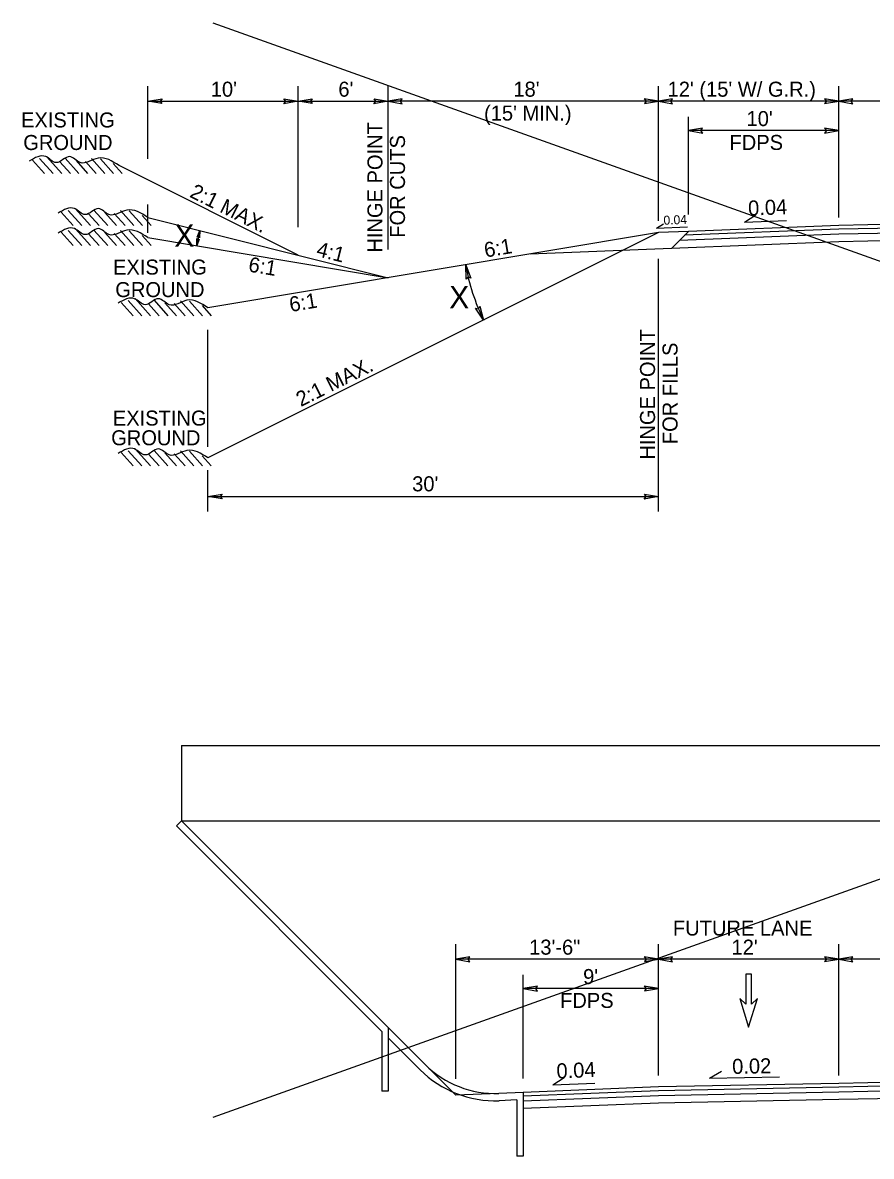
# Model space of a CAD drawing. Extents: x 1553195 to 1553792, y 810516 to 810787.
# Drawn here: x 1553435.9 to 1553492.4, y 810531.1 to 810606.6 of the extents above; entities that cross this region are included whole.
import ezdxf

# ---------------------------------------------------------------- set-up
doc = ezdxf.new("R2010")
doc.units = 0
for name, color, linetype in [('Prop Dimension', 7, 'Continuous'), ('Prop DSN Text', 7, 'Continuous'), ('Prop Pavement Schedule Description CELL', 7, 'Continuous'), ('Prop Typical Section', 7, 'Continuous'), ('Sheet Sticker Incomplete CELL', 7, 'Continuous'), ('Typical Arrow Superelevation CELL', 7, 'Continuous'), ('Typical Pavement Slope CELL', 7, 'Continuous'), ('Typical Text General CELL', 7, 'Continuous'), ('z - Construction', 7, 'Continuous')]:
    doc.layers.add(name, color=color, linetype=linetype)

msp = doc.modelspace()

# ---------------------------------------------------------------- linework, layer by layer
at = {"layer": 'Prop Dimension'}
for p, q in [((1553483.925, 810593.325), (1553484.698, 810593.813)), ((1553483.925, 810593.325), (1553486.72, 810593.436)), ((1553478.066, 810592.922), (1553478.53, 810593.215)), ((1553478.066, 810592.922), (1553480.136, 810593.004)), ((1553481.608, 810536.34), (1553482.391, 810536.814)), ((1553471.163, 810535.891), (1553471.936, 810536.38)), ((1553471.163, 810535.891), (1553473.958, 810536.003)), ((1553481.608, 810536.34), (1553486.268, 810536.434))]:
    msp.add_line(p, q, dxfattribs=at)
at = {"layer": 'Prop DSN Text'}
for points in [[(1553445.143, 810601.212), (1553444.206, 810601.374), (1553445.148, 810601.54), (1553445.028, 810601.374)], [(1553453.268, 810601.535), (1553454.206, 810601.374), (1553453.263, 810601.207), (1553453.383, 810601.374)], [(1553455.143, 810601.212), (1553454.206, 810601.374), (1553455.148, 810601.54), (1553455.028, 810601.374)], [(1553459.268, 810601.535), (1553460.206, 810601.374), (1553459.263, 810601.207), (1553459.383, 810601.374)], [(1553461.143, 810601.535), (1553460.206, 810601.374), (1553461.148, 810601.207), (1553461.028, 810601.374)], [(1553477.268, 810601.212), (1553478.206, 810601.374), (1553477.263, 810601.54), (1553477.383, 810601.374)], [(1553479.143, 810601.535), (1553478.206, 810601.374), (1553479.148, 810601.207), (1553479.028, 810601.374)], [(1553489.268, 810601.212), (1553490.206, 810601.374), (1553489.263, 810601.54), (1553489.383, 810601.374)], [(1553491.143, 810601.535), (1553490.206, 810601.374), (1553491.148, 810601.207), (1553491.028, 810601.374)], [(1553481.143, 810599.579), (1553480.206, 810599.418), (1553481.148, 810599.251), (1553481.028, 810599.418)], [(1553489.268, 810599.257), (1553490.206, 810599.418), (1553489.263, 810599.585), (1553489.383, 810599.418)], [(1553447.488, 810592.322), (1553447.675, 810592.76), (1553447.647, 810592.282), (1553447.58, 810592.36)], [(1553447.63, 810592.197), (1553447.465, 810591.751), (1553447.469, 810592.229), (1553447.54, 810592.155)], [(1553465.394, 810589.537), (1553465.368, 810590.488), (1553465.717, 810589.596), (1553465.53, 810589.681)], [(1553466.319, 810587.726), (1553466.565, 810586.807), (1553466.019, 810587.593), (1553466.221, 810587.554)], [(1553449.143, 810574.9), (1553448.206, 810575.062), (1553449.148, 810575.228), (1553449.028, 810575.062)], [(1553477.268, 810575.223), (1553478.206, 810575.062), (1553477.263, 810574.895), (1553477.383, 810575.062)], [(1553465.643, 810544.426), (1553464.706, 810544.264), (1553465.648, 810544.098), (1553465.528, 810544.264)], [(1553477.268, 810544.103), (1553478.206, 810544.264), (1553477.263, 810544.431), (1553477.383, 810544.264)], [(1553479.143, 810544.426), (1553478.206, 810544.264), (1553479.148, 810544.098), (1553479.028, 810544.264)], [(1553489.268, 810544.103), (1553490.206, 810544.264), (1553489.263, 810544.431), (1553489.383, 810544.264)], [(1553491.143, 810544.426), (1553490.206, 810544.264), (1553491.148, 810544.098), (1553491.028, 810544.264)], [(1553470.143, 810542.47), (1553469.206, 810542.309), (1553470.148, 810542.142), (1553470.028, 810542.309)], [(1553477.268, 810542.147), (1553478.206, 810542.309), (1553477.263, 810542.476), (1553477.383, 810542.309)]]:
    msp.add_lwpolyline(points, close=True, dxfattribs=at)
at = {"layer": 'Prop Pavement Schedule Description CELL'}
for p, q in [((1553460.206, 810591.507), (1553460.206, 810602.374)), ((1553478.206, 810593.404), (1553478.206, 810602.374)), ((1553480.206, 810593.822), (1553480.206, 810600.332)), ((1553478.206, 810574.062), (1553478.206, 810590.871)), ((1553448.206, 810578.372), (1553448.206, 810586.148)), ((1553448.206, 810574.062), (1553448.206, 810576.817)), ((1553464.706, 810536.295), (1553464.706, 810545.264))]:
    msp.add_line(p, q, dxfattribs=at)
for centre, radius, start, end in [((1553460.206, 810589.627), 12.916, 165.96376, 170.53768), ((1553478.206, 810592.627), 13.014, 189.46232, 206.56505)]:
    msp.add_arc(centre, radius, start, end, dxfattribs=at)
at = {"layer": 'Prop Typical Section'}
msp.add_lwpolyline([(1553484.799, 810541.639), (1553484.393, 810541.264), (1553484.393, 810543.264), (1553484.018, 810543.264), (1553484.018, 810541.264), (1553483.612, 810541.639), (1553484.206, 810539.733)], close=True, dxfattribs=at)
at = {"layer": 'Sheet Sticker Incomplete CELL'}
for p, q in [((1553454.206, 810591.127), (1553442.287, 810597.087)), ((1553444.206, 810593.627), (1553460.206, 810589.627)), ((1553478.206, 810592.627), (1553448.206, 810587.627)), ((1553478.206, 810592.627), (1553448.206, 810577.627)), ((1553480.206, 810592.707), (1553478.206, 810592.627)), ((1553444.206, 810592.294), (1553460.206, 810589.627)), ((1553479.077, 810591.579), (1553469.653, 810591.202))]:
    msp.add_line(p, q, dxfattribs=at)
at = {"layer": 'Typical Arrow Superelevation CELL'}
for p, q in [((1553652.472, 810606.601), (1553448.543, 810533.73)), ((1553448.543, 810606.601), (1553652.472, 810533.73)), ((1553446.448, 810558.478), (1553641.963, 810558.478)), ((1553446.448, 810558.478), (1553446.448, 810553.478)), ((1553446.448, 810553.478), (1553446.103, 810553.133)), ((1553446.448, 810553.478), (1553641.963, 810553.478)), ((1553462.672, 810537.254), (1553446.448, 810553.478)), ((1553459.784, 810539.452), (1553446.103, 810553.133)), ((1553459.784, 810539.452), (1553459.784, 810535.478)), ((1553460.206, 810539.687), (1553460.206, 810535.478)), ((1553462.327, 810536.908), (1553460.206, 810539.03)), ((1553464.706, 810535.22), (1553462.672, 810537.254)), ((1553460.206, 810535.478), (1553459.784, 810535.478)), ((1553467.579, 810535.334), (1553464.706, 810535.22)), ((1553469.206, 810535.398), (1553467.579, 810535.334)), ((1553469.206, 810535.398), (1553469.206, 810531.142)), ((1553468.784, 810534.893), (1553467.598, 810534.846)), ((1553468.784, 810534.893), (1553468.784, 810531.142)), ((1553469.206, 810531.142), (1553468.784, 810531.142))]:
    msp.add_line(p, q, dxfattribs=at)
for radius in [7.06, 6.572]:
    msp.add_arc((1553467.32, 810541.901), radius, 225, 272.26207, dxfattribs=at)
at = {"layer": 'Typical Pavement Slope CELL'}
for p, q in [((1553514.206, 810593.587), (1553490.206, 810593.107)), ((1553480.206, 810592.707), (1553479.077, 810591.579)), ((1553490.206, 810592.857), (1553479.945, 810592.447)), ((1553490.206, 810593.107), (1553480.206, 810592.707)), ((1553514.206, 810593.337), (1553490.206, 810592.857)), ((1553514.206, 810593.004), (1553490.206, 810592.524)), ((1553490.206, 810592.024), (1553479.077, 810591.579)), ((1553490.206, 810592.524), (1553479.598, 810592.099)), ((1553514.206, 810592.504), (1553490.206, 810592.024)), ((1553490.206, 810535.998), (1553478.206, 810535.758)), ((1553514.206, 810536.478), (1553490.206, 810535.998)), ((1553514.206, 810536.228), (1553490.206, 810535.748)), ((1553478.206, 810535.758), (1553469.206, 810535.398)), ((1553478.206, 810535.508), (1553469.206, 810535.148)), ((1553490.206, 810535.748), (1553478.206, 810535.508)), ((1553490.206, 810535.415), (1553478.206, 810535.175)), ((1553514.206, 810535.895), (1553490.206, 810535.415)), ((1553514.206, 810535.395), (1553490.206, 810534.915)), ((1553478.206, 810535.175), (1553469.206, 810534.815)), ((1553478.206, 810534.675), (1553469.206, 810534.315)), ((1553490.206, 810534.915), (1553478.206, 810534.675))]:
    msp.add_line(p, q, dxfattribs=at)
at = {"layer": 'Typical Text General CELL'}
for p, q in [((1553436.52, 810597.443), (1553437.317, 810596.556)), ((1553436.982, 810597.569), (1553437.893, 810596.556)), ((1553437.448, 810597.692), (1553438.469, 810596.556)), ((1553438.335, 810597.345), (1553439.045, 810596.556)), ((1553438.696, 810597.585), (1553439.621, 810596.556)), ((1553439.422, 810597.419), (1553440.197, 810596.556)), ((1553440.045, 810597.366), (1553440.773, 810596.556)), ((1553440.455, 810597.55), (1553441.349, 810596.556)), ((1553441.051, 810597.529), (1553441.925, 810596.556)), ((1553441.9, 810597.225), (1553442.501, 810596.556)), ((1553438.901, 810594.11), (1553439.812, 810593.097)), ((1553439.367, 810594.232), (1553440.388, 810593.097)), ((1553440.615, 810594.125), (1553441.54, 810593.097)), ((1553438.439, 810593.983), (1553439.236, 810593.097)), ((1553440.254, 810593.886), (1553440.964, 810593.097)), ((1553441.34, 810593.959), (1553442.116, 810593.097)), ((1553441.964, 810593.906), (1553442.692, 810593.097)), ((1553442.374, 810594.091), (1553443.268, 810593.097)), ((1553442.97, 810594.069), (1553443.844, 810593.097)), ((1553443.819, 810593.765), (1553444.42, 810593.097)), ((1553438.439, 810592.65), (1553439.236, 810591.764)), ((1553438.901, 810592.776), (1553439.812, 810591.764)), ((1553439.367, 810592.899), (1553440.388, 810591.764)), ((1553440.615, 810592.792), (1553441.54, 810591.764)), ((1553441.34, 810592.626), (1553442.116, 810591.764)), ((1553442.374, 810592.757), (1553443.268, 810591.764)), ((1553442.97, 810592.736), (1553443.844, 810591.764)), ((1553440.254, 810592.553), (1553440.964, 810591.764)), ((1553441.964, 810592.573), (1553442.692, 810591.764)), ((1553443.819, 810592.432), (1553444.42, 810591.764)), ((1553442.901, 810588.11), (1553443.812, 810587.097)), ((1553443.367, 810588.232), (1553444.388, 810587.097)), ((1553444.615, 810588.125), (1553445.54, 810587.097)), ((1553446.374, 810588.091), (1553447.268, 810587.097)), ((1553446.97, 810588.069), (1553447.844, 810587.097)), ((1553442.439, 810587.983), (1553443.236, 810587.097)), ((1553444.254, 810587.886), (1553444.964, 810587.097)), ((1553445.34, 810587.959), (1553446.116, 810587.097)), ((1553445.964, 810587.906), (1553446.692, 810587.097)), ((1553447.819, 810587.765), (1553448.42, 810587.097)), ((1553442.439, 810577.983), (1553443.236, 810577.097)), ((1553442.901, 810578.11), (1553443.812, 810577.097)), ((1553443.367, 810578.232), (1553444.388, 810577.097)), ((1553444.254, 810577.886), (1553444.964, 810577.097)), ((1553444.615, 810578.125), (1553445.54, 810577.097)), ((1553445.34, 810577.959), (1553446.116, 810577.097)), ((1553445.964, 810577.906), (1553446.692, 810577.097)), ((1553446.374, 810578.091), (1553447.268, 810577.097)), ((1553446.97, 810578.069), (1553447.844, 810577.097)), ((1553447.819, 810577.765), (1553448.42, 810577.097))]:
    msp.add_line(p, q, dxfattribs=at)
for points in [[(1553442.287, 810597.087), (1553440.892, 810597.585), (1553439.697, 810597.286), (1553439, 810597.685), (1553438.104, 810597.286), (1553437.407, 810597.685), (1553436.311, 810597.386)], [(1553444.206, 810593.627), (1553442.811, 810594.126), (1553441.616, 810593.827), (1553440.919, 810594.225), (1553440.023, 810593.827), (1553439.326, 810594.225), (1553438.23, 810593.926)], [(1553444.206, 810592.294), (1553442.811, 810592.792), (1553441.616, 810592.493), (1553440.919, 810592.892), (1553440.023, 810592.493), (1553439.326, 810592.892), (1553438.23, 810592.593)], [(1553448.206, 810587.627), (1553446.811, 810588.126), (1553445.616, 810587.827), (1553444.919, 810588.225), (1553444.023, 810587.827), (1553443.326, 810588.225), (1553442.23, 810587.926)], [(1553448.206, 810577.627), (1553446.811, 810578.126), (1553445.616, 810577.827), (1553444.919, 810578.225), (1553444.023, 810577.827), (1553443.326, 810578.225), (1553442.23, 810577.926)]]:
    msp.add_spline(points, degree=3, dxfattribs=at)
at = {"layer": 'z - Construction'}
for p, q in [((1553444.206, 810597.541), (1553444.206, 810602.374)), ((1553454.206, 810592.994), (1553454.206, 810602.374)), ((1553490.206, 810593.627), (1553490.206, 810602.374)), ((1553444.206, 810601.374), (1553454.206, 810601.374)), ((1553454.206, 810601.374), (1553460.206, 810601.374)), ((1553478.206, 810601.374), (1553460.206, 810601.374)), ((1553490.206, 810601.374), (1553478.206, 810601.374)), ((1553502.206, 810601.374), (1553490.206, 810601.374)), ((1553490.206, 810599.418), (1553480.206, 810599.418)), ((1553444.206, 810592.603), (1553444.206, 810594.493)), ((1553448.206, 810575.062), (1553478.206, 810575.062)), ((1553478.206, 810536.518), (1553478.206, 810545.264)), ((1553490.206, 810536.518), (1553490.206, 810545.264)), ((1553478.206, 810544.264), (1553464.706, 810544.264)), ((1553490.206, 810544.264), (1553478.206, 810544.264)), ((1553502.206, 810544.264), (1553490.206, 810544.264)), ((1553469.206, 810536.314), (1553469.206, 810543.223)), ((1553478.206, 810542.309), (1553469.206, 810542.309))]:
    msp.add_line(p, q, dxfattribs=at)

# ---------------------------------------------------------------- texts
at = {"layer": 'Prop Pavement Schedule Description CELL'}
for s, height, p in [("10'", 1, (1553448.395, 810601.674)), ("6'", 1, (1553456.89, 810601.674)), ("18'", 1, (1553468.545, 810601.674)), ("12' (15' W/ G.R.)", 1, (1553478.814, 810601.674)), ("(15' MIN.)", 1, (1553466.592, 810600.086)), ('EXISTING', 1, (1553435.76, 810599.625)), ("10'", 1, (1553484.068, 810599.718)), ('GROUND', 1, (1553435.91, 810598.125)), ('FDPS', 1, (1553482.933, 810598.129)), ('X', 1.5, (1553445.966, 810591.684)), ('EXISTING', 1, (1553441.887, 810589.833)), ('GROUND', 1, (1553442.036, 810588.333)), ('X', 1.5, (1553464.269, 810587.58)), ('EXISTING', 1, (1553441.874, 810579.782)), ('GROUND', 1, (1553441.764, 810578.471)), ("30'", 1, (1553461.804, 810575.406)), ('FUTURE LANE', 1, (1553479.167, 810545.837)), ('13\'-6"', 1, (1553469.595, 810544.565)), ("12'", 1, (1553483.068, 810544.565)), ("9'", 1, (1553473.187, 810542.609)), ('FDPS', 1, (1553471.653, 810541.019))]:
    msp.add_text(s, height=height, dxfattribs=at).set_placement(p)
for s, height, rotation, p in [('HINGE POINT', 1, 90, (1553459.827, 810591.292)), ('FOR CUTS', 1, 90, (1553461.327, 810592.285)), ('2:1 MAX.', 1, 333.43495, (1553446.928, 810595.031)), ('0.04', 1, 2.29061, (1553484.194, 810593.753)), ('0.04', 0.6, 2.29061, (1553478.551, 810593.147)), ('4:1', 1, 345.96376, (1553455.368, 810591.077)), ('6:1', 1, 9.46232, (1553466.684, 810590.963)), ('6:1', 1, 350.53768, (1553450.853, 810590.041)), ('6:1', 1, 9.46232, (1553453.711, 810587.341)), ('HINGE POINT', 1, 90, (1553477.975, 810577.513)), ('FOR FILLS', 1, 90, (1553479.475, 810578.545)), ('2:1 MAX.', 1, 26.56505, (1553454.392, 810581.015)), ('0.02', 1, 1.14587, (1553483.122, 810536.624)), ('0.04', 1, 2.29061, (1553471.432, 810536.32))]:
    msp.add_text(s, height=height, rotation=rotation, dxfattribs=at).set_placement(p)

doc.saveas('drawing.dxf')
